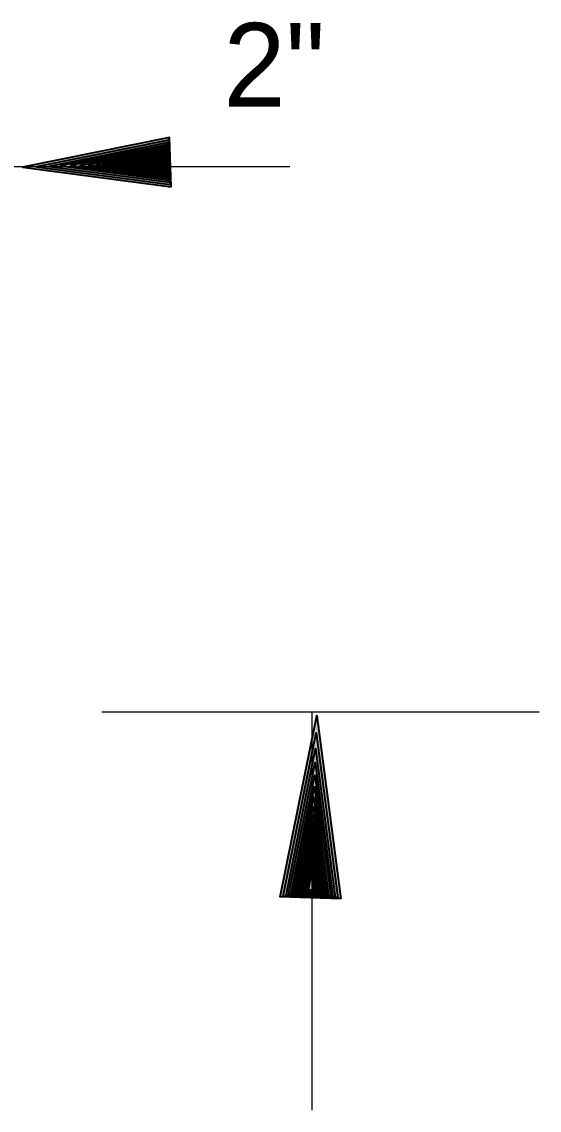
# Model space of a CAD drawing. Extents: x 895.6 to 930.4, y -2278.6 to -2254.7.
# Drawn here: x 922.812 to 923.608, y -2261.407 to -2259.732 of the extents above; entities that cross this region are included whole.
import ezdxf

# ---------------------------------------------------------------- set-up
doc = ezdxf.new("R2010")
doc.units = 0
doc.header["$LTSCALE"] = 0.051
doc.layers.add('1', color=7, linetype='Continuous', lineweight=70)
doc.layers.add('3', color=7, linetype='Continuous', lineweight=40)

msp = doc.modelspace()

# ---------------------------------------------------------------- hatches: boundary and pattern name
at = {"layer": '3'}
for points in [[(923.04125, -2259.98617), (923.03875, -2259.91025), (922.81258, -2259.95592), (922.81258, -2259.95592)], [(923.04008, -2259.98225), (923.03783, -2259.91417), (922.83433, -2259.95517), (922.83433, -2259.95517)], [(923.03908, -2259.97892), (923.03708, -2259.91758), (922.85383, -2259.95458), (922.85383, -2259.95458)], [(923.03808, -2259.97583), (923.03625, -2259.92075), (922.87142, -2259.95392), (922.87142, -2259.95392)], [(923.03733, -2259.97333), (923.03558, -2259.92367), (922.88725, -2259.95342), (922.88725, -2259.95342)], [(923.03633, -2259.97075), (923.03492, -2259.92608), (922.90142, -2259.95308), (922.90142, -2259.95308)], [(923.03583, -2259.96858), (923.03458, -2259.92817), (922.91425, -2259.95242), (922.91425, -2259.95242)], [(923.03517, -2259.96667), (923.03408, -2259.93033), (922.92592, -2259.95225), (922.92592, -2259.95225)], [(923.03475, -2259.96483), (923.03358, -2259.93208), (922.93625, -2259.95167), (922.93625, -2259.95167)], [(923.03417, -2259.96317), (923.03308, -2259.93367), (922.94558, -2259.95158), (922.94558, -2259.95158)], [(923.03367, -2259.96167), (923.03275, -2259.93533), (922.95408, -2259.95117), (922.95408, -2259.95117)], [(923.03333, -2259.96033), (923.03242, -2259.93667), (922.96158, -2259.95075), (922.96158, -2259.95075)], [(923.03283, -2259.95925), (923.03225, -2259.93775), (922.96858, -2259.95067), (922.96858, -2259.95067)], [(923.03242, -2259.95808), (923.03192, -2259.93883), (922.97442, -2259.95058), (922.97442, -2259.95058)], [(923.03225, -2259.95717), (923.03167, -2259.93983), (922.98008, -2259.95033), (922.98008, -2259.95033)], [(923.03192, -2259.95633), (923.03158, -2259.94067), (922.98492, -2259.94992), (922.98492, -2259.94992)], [(923.03175, -2259.95558), (923.03125, -2259.94133), (922.98942, -2259.94983), (922.98942, -2259.94983)], [(923.03158, -2259.95475), (923.03117, -2259.94217), (922.99333, -2259.94975), (922.99333, -2259.94975)], [(923.03125, -2259.95433), (923.03092, -2259.94283), (922.99692, -2259.94975), (922.99692, -2259.94975)], [(923.03108, -2259.95383), (923.03075, -2259.94342), (923.00017, -2259.94975), (923.00017, -2259.94975)], [(923.03083, -2259.95342), (923.03058, -2259.94425), (923.00308, -2259.94983), (923.00308, -2259.94983)], [(923.03083, -2259.95292), (923.03058, -2259.94467), (923.00567, -2259.94975), (923.00567, -2259.94975)], [(923.03067, -2259.95242), (923.03033, -2259.94508), (923.00808, -2259.94942), (923.00808, -2259.94942)], [(923.03058, -2259.95225), (923.03025, -2259.94558), (923.01017, -2259.94958), (923.01017, -2259.94958)], [(923.30275, -2261.08217), (923.20917, -2261.07892), (923.26542, -2260.79975), (923.26542, -2260.79975)], [(923.29808, -2261.08067), (923.21383, -2261.07783), (923.26442, -2260.82667), (923.26442, -2260.82667)], [(923.29383, -2261.07942), (923.21817, -2261.07683), (923.26375, -2260.85075), (923.26375, -2260.85075)], [(923.29017, -2261.07825), (923.22208, -2261.07592), (923.26308, -2260.87242), (923.26308, -2260.87242)], [(923.28692, -2261.07733), (923.22558, -2261.07517), (923.26242, -2260.89192), (923.26242, -2260.89192)], [(923.28375, -2261.07617), (923.22858, -2261.07433), (923.26183, -2260.90958), (923.26183, -2260.90958)], [(923.28092, -2261.07542), (923.23125, -2261.07383), (923.26125, -2260.92533), (923.26125, -2260.92533)], [(923.27867, -2261.07458), (923.23383, -2261.07325), (923.26083, -2260.93975), (923.26083, -2260.93975)], [(923.27642, -2261.07417), (923.23608, -2261.07258), (923.26025, -2260.95242), (923.26025, -2260.95242)], [(923.27433, -2261.07333), (923.23792, -2261.07208), (923.25992, -2260.96408), (923.25992, -2260.96408)], [(923.27258, -2261.07275), (923.23992, -2261.07167), (923.25958, -2260.97442), (923.25958, -2260.97442)], [(923.27083, -2261.07233), (923.24167, -2261.07125), (923.25917, -2260.98375), (923.25917, -2260.98375)], [(923.26958, -2261.07175), (923.24308, -2261.07092), (923.25892, -2260.99233), (923.25892, -2260.99233)], [(923.26817, -2261.07125), (923.24433, -2261.07067), (923.25875, -2260.99967), (923.25875, -2260.99967)], [(923.26708, -2261.07092), (923.24558, -2261.07025), (923.25858, -2261.00658), (923.25858, -2261.00658)], [(923.26592, -2261.07067), (923.24658, -2261.07017), (923.25817, -2261.01267), (923.25817, -2261.01267)], [(923.26492, -2261.07033), (923.24742, -2261.06975), (923.25792, -2261.01817), (923.25792, -2261.01817)], [(923.26408, -2261.07017), (923.24842, -2261.06967), (923.25783, -2261.02308), (923.25783, -2261.02308)], [(923.26358, -2261.06975), (923.24933, -2261.06942), (923.25783, -2261.02742), (923.25783, -2261.02742)], [(923.26283, -2261.06958), (923.25017, -2261.06917), (923.25775, -2261.03133), (923.25775, -2261.03133)], [(923.26242, -2261.06925), (923.25092, -2261.06883), (923.25792, -2261.03492), (923.25792, -2261.03492)], [(923.26175, -2261.06925), (923.25158, -2261.06883), (923.25775, -2261.03825), (923.25775, -2261.03825)], [(923.26117, -2261.06908), (923.25208, -2261.06867), (923.25742, -2261.04117), (923.25742, -2261.04117)], [(923.26083, -2261.06883), (923.25267, -2261.06858), (923.25758, -2261.04375), (923.25758, -2261.04375)]]:
    msp.add_hatch(color=256, dxfattribs=at).paths.add_polyline_path(points)

# ---------------------------------------------------------------- linework, layer by layer
at = {"layer": '1', "lineweight": 25}
for p, q in [((923.22417, -2259.95542), (921.53067, -2259.95542)), ((923.60783, -2260.79483), (922.93483, -2260.79483)), ((923.25867, -2261.40742), (923.25867, -2260.79433))]:
    msp.add_line(p, q, dxfattribs=at)
at = {"layer": '3'}
for points in [[(923.04125, -2259.98617), (923.03875, -2259.91025), (922.81258, -2259.95592), (922.81258, -2259.95592)], [(923.04008, -2259.98225), (923.03783, -2259.91417), (922.83433, -2259.95517), (922.83433, -2259.95517)], [(923.03908, -2259.97892), (923.03708, -2259.91758), (922.85383, -2259.95458), (922.85383, -2259.95458)], [(923.03808, -2259.97583), (923.03625, -2259.92075), (922.87142, -2259.95392), (922.87142, -2259.95392)], [(923.03733, -2259.97333), (923.03558, -2259.92367), (922.88725, -2259.95342), (922.88725, -2259.95342)], [(923.03633, -2259.97075), (923.03492, -2259.92608), (922.90142, -2259.95308), (922.90142, -2259.95308)], [(923.03583, -2259.96858), (923.03458, -2259.92817), (922.91425, -2259.95242), (922.91425, -2259.95242)], [(923.03517, -2259.96667), (923.03408, -2259.93033), (922.92592, -2259.95225), (922.92592, -2259.95225)], [(923.03475, -2259.96483), (923.03358, -2259.93208), (922.93625, -2259.95167), (922.93625, -2259.95167)], [(923.03417, -2259.96317), (923.03308, -2259.93367), (922.94558, -2259.95158), (922.94558, -2259.95158)], [(923.03367, -2259.96167), (923.03275, -2259.93533), (922.95408, -2259.95117), (922.95408, -2259.95117)], [(923.03333, -2259.96033), (923.03242, -2259.93667), (922.96158, -2259.95075), (922.96158, -2259.95075)], [(923.03283, -2259.95925), (923.03225, -2259.93775), (922.96858, -2259.95067), (922.96858, -2259.95067)], [(923.03242, -2259.95808), (923.03192, -2259.93883), (922.97442, -2259.95058), (922.97442, -2259.95058)], [(923.03225, -2259.95717), (923.03167, -2259.93983), (922.98008, -2259.95033), (922.98008, -2259.95033)], [(923.03192, -2259.95633), (923.03158, -2259.94067), (922.98492, -2259.94992), (922.98492, -2259.94992)], [(923.03175, -2259.95558), (923.03125, -2259.94133), (922.98942, -2259.94983), (922.98942, -2259.94983)], [(923.03158, -2259.95475), (923.03117, -2259.94217), (922.99333, -2259.94975), (922.99333, -2259.94975)], [(923.03125, -2259.95433), (923.03092, -2259.94283), (922.99692, -2259.94975), (922.99692, -2259.94975)], [(923.03108, -2259.95383), (923.03075, -2259.94342), (923.00017, -2259.94975), (923.00017, -2259.94975)], [(923.03083, -2259.95342), (923.03058, -2259.94425), (923.00308, -2259.94983), (923.00308, -2259.94983)], [(923.03083, -2259.95292), (923.03058, -2259.94467), (923.00567, -2259.94975), (923.00567, -2259.94975)], [(923.03067, -2259.95242), (923.03033, -2259.94508), (923.00808, -2259.94942), (923.00808, -2259.94942)], [(923.03058, -2259.95225), (923.03025, -2259.94558), (923.01017, -2259.94958), (923.01017, -2259.94958)], [(923.30275, -2261.08217), (923.20917, -2261.07892), (923.26542, -2260.79975), (923.26542, -2260.79975)], [(923.29808, -2261.08067), (923.21383, -2261.07783), (923.26442, -2260.82667), (923.26442, -2260.82667)], [(923.29383, -2261.07942), (923.21817, -2261.07683), (923.26375, -2260.85075), (923.26375, -2260.85075)], [(923.29017, -2261.07825), (923.22208, -2261.07592), (923.26308, -2260.87242), (923.26308, -2260.87242)], [(923.28692, -2261.07733), (923.22558, -2261.07517), (923.26242, -2260.89192), (923.26242, -2260.89192)], [(923.28375, -2261.07617), (923.22858, -2261.07433), (923.26183, -2260.90958), (923.26183, -2260.90958)], [(923.28092, -2261.07542), (923.23125, -2261.07383), (923.26125, -2260.92533), (923.26125, -2260.92533)], [(923.27867, -2261.07458), (923.23383, -2261.07325), (923.26083, -2260.93975), (923.26083, -2260.93975)], [(923.27642, -2261.07417), (923.23608, -2261.07258), (923.26025, -2260.95242), (923.26025, -2260.95242)], [(923.27433, -2261.07333), (923.23792, -2261.07208), (923.25992, -2260.96408), (923.25992, -2260.96408)], [(923.27258, -2261.07275), (923.23992, -2261.07167), (923.25958, -2260.97442), (923.25958, -2260.97442)], [(923.27083, -2261.07233), (923.24167, -2261.07125), (923.25917, -2260.98375), (923.25917, -2260.98375)], [(923.26958, -2261.07175), (923.24308, -2261.07092), (923.25892, -2260.99233), (923.25892, -2260.99233)], [(923.26817, -2261.07125), (923.24433, -2261.07067), (923.25875, -2260.99967), (923.25875, -2260.99967)], [(923.26708, -2261.07092), (923.24558, -2261.07025), (923.25858, -2261.00658), (923.25858, -2261.00658)], [(923.26592, -2261.07067), (923.24658, -2261.07017), (923.25817, -2261.01267), (923.25817, -2261.01267)], [(923.26492, -2261.07033), (923.24742, -2261.06975), (923.25792, -2261.01817), (923.25792, -2261.01817)], [(923.26408, -2261.07017), (923.24842, -2261.06967), (923.25783, -2261.02308), (923.25783, -2261.02308)], [(923.26358, -2261.06975), (923.24933, -2261.06942), (923.25783, -2261.02742), (923.25783, -2261.02742)], [(923.26283, -2261.06958), (923.25017, -2261.06917), (923.25775, -2261.03133), (923.25775, -2261.03133)], [(923.26242, -2261.06925), (923.25092, -2261.06883), (923.25792, -2261.03492), (923.25792, -2261.03492)], [(923.26175, -2261.06925), (923.25158, -2261.06883), (923.25775, -2261.03825), (923.25775, -2261.03825)], [(923.26117, -2261.06908), (923.25208, -2261.06867), (923.25742, -2261.04117), (923.25742, -2261.04117)], [(923.26083, -2261.06883), (923.25267, -2261.06858), (923.25758, -2261.04375), (923.25758, -2261.04375)]]:
    msp.add_lwpolyline(points, close=True, dxfattribs=at)

# ---------------------------------------------------------------- texts
at = {"layer": '1'}
msp.add_text('2"', height=0.1286, dxfattribs=at).set_placement((923.12192, -2259.8625))

doc.saveas('drawing.dxf')
